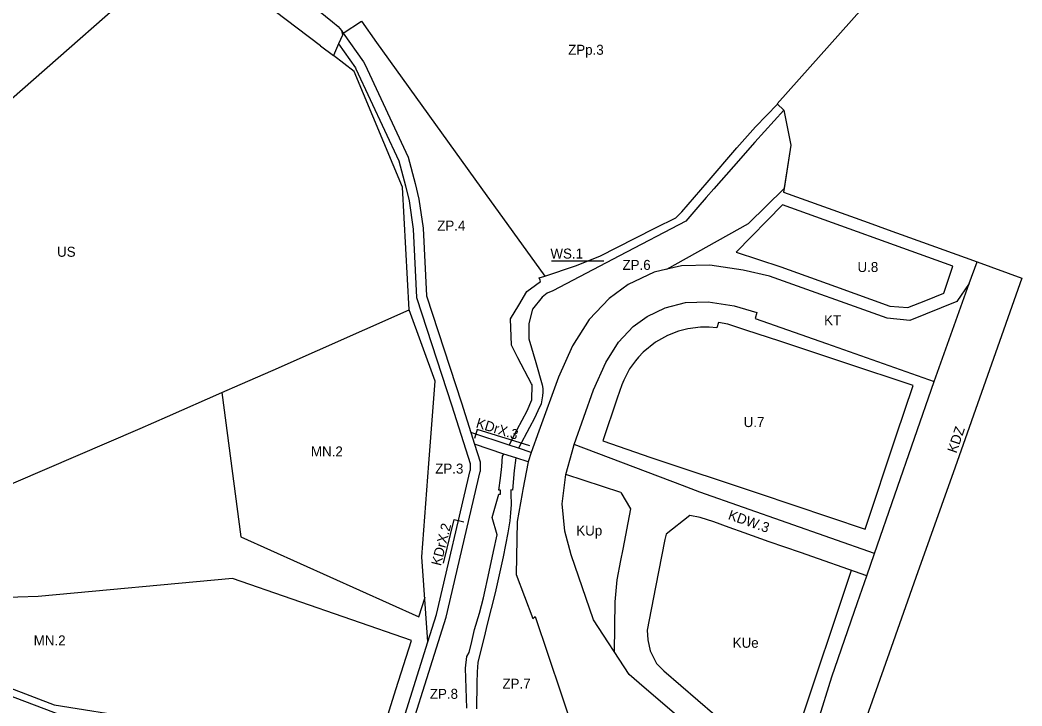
# Model space of a CAD drawing. Extents: x 7422426 to 7423369, y 5542157 to 5542988.
# Drawn here: x 7422842.1 to 7423243.7, y 5542435.8 to 5542710.7 of the extents above; entities that cross this region are included whole.
import ezdxf

# ---------------------------------------------------------------- set-up
doc = ezdxf.new("R2010")
doc.units = 0
for name, color, linetype in [('GRANICA OBSZARU OBJĘTEGO PLANEM', 7, 'Continuous'), ('LINIE ROZGRANICZAJĄCE TERENY O RÓŻNYM PRZEZNACZENIU LUB RÓŻNYCH ZASADACH ZAGOSPODAROWANIA', 7, 'Continuous'), ('NIEPRZEKRACZALNA LINIA ZABUDOWY', 7, 'Continuous'), ('OBOWIĄZUJĄCA LINIA ZABUDOWY', 7, 'Continuous'), ('OZNACZENIA TERENÓW', 7, 'Continuous')]:
    doc.layers.add(name, color=color, linetype=linetype)

msp = doc.modelspace()

# ---------------------------------------------------------------- linework, layer by layer
at = {"layer": 'GRANICA OBSZARU OBJĘTEGO PLANEM'}
for p, q in [((7423179.79, 5542715.52), (7423145.58, 5542677.06)), ((7423145.58, 5542677.06), (7423148.22, 5542674.57)), ((7423148.22, 5542674.57), (7423150.99, 5542660.52)), ((7423150.99, 5542660.52), (7423148.13, 5542641.73)), ((7423148.13, 5542641.73), (7423182.09, 5542629.5)), ((7423182.09, 5542629.5), (7423190.12, 5542626.62)), ((7423190.12, 5542626.62), (7423220.94, 5542615.53)), ((7423220.94, 5542615.53), (7423225.67, 5542613.82)), ((7423225.67, 5542613.82), (7423243.69, 5542607.21)), ((7423243.69, 5542607.21), (7423216.87, 5542531.51)), ((7423243.69, 5542607.21), (7423243.69, 5542607.21)), ((7423216.87, 5542531.51), (7423201.18, 5542487.24))]:
    msp.add_line(p, q, dxfattribs=at)
msp.add_lwpolyline([(7423201.18, 5542487.24), (7423190.43, 5542456.94), (7423177.58, 5542420.71), (7423161.25, 5542374.63), (7423114.75, 5542243.43), (7423108.16, 5542225.13)], dxfattribs=at)
at = {"layer": 'LINIE ROZGRANICZAJĄCE TERENY O RÓŻNYM PRZEZNACZENIU LUB RÓŻNYCH ZASADACH ZAGOSPODAROWANIA'}
for p, q in [((7423179.79, 5542715.52), (7423145.58, 5542677.06)), ((7422970.89, 5542706.45), (7422971.61, 5542705.43)), ((7422971.61, 5542705.43), (7422979.75, 5542693.91)), ((7422962.53, 5542700.33), (7422967.67, 5542696.44)), ((7422969.75, 5542701.14), (7422976.49, 5542691.61)), ((7422976.49, 5542691.61), (7422976.65, 5542691.2)), ((7423148.22, 5542674.57), (7423150.99, 5542660.52)), ((7423148.13, 5542641.73), (7423182.09, 5542629.5)), ((7423182.09, 5542629.5), (7423190.12, 5542626.62)), ((7423190.12, 5542626.62), (7423220.94, 5542615.53)), ((7423220.94, 5542615.53), (7423225.67, 5542613.82)), ((7423225.67, 5542613.82), (7423243.69, 5542607.21)), ((7423243.69, 5542607.21), (7423216.87, 5542531.51)), ((7423243.69, 5542607.21), (7423243.69, 5542607.21)), ((7423038.09, 5542540.32), (7423022.74, 5542545.46)), ((7423022.74, 5542545.46), (7423024.23, 5542540.7)), ((7423041.91, 5542539.06), (7423038.09, 5542540.32)), ((7423047.01, 5542537.37), (7423041.91, 5542539.06)), ((7423045.69, 5542533.59), (7423040.75, 5542535.21)), ((7423216.87, 5542531.51), (7423201.18, 5542487.24)), ((7423026.51, 5542530.19), (7423026.46, 5542529.73)), ((7423082.89, 5542521.3), (7423086.74, 5542514.76)), ((7423005.58, 5542461.55), (7423003.1, 5542495.57))]:
    msp.add_line(p, q, dxfattribs=at)
for points in [[(7422832.16, 5542800.69), (7422847.42, 5542791.25), (7422853.13, 5542787.77), (7422861.66, 5542782.48), (7422867.97, 5542778.93), (7422873.51, 5542775.58), (7422899.93, 5542760.62), (7422913.83, 5542750.93), (7422919.53, 5542746.93), (7422923.11, 5542744.51), (7422926.94, 5542741.99), (7422928.96, 5542740.48), (7422930.97, 5542738.96), (7422933.02, 5542737.32), (7422956.03, 5542718.92), (7422961.65, 5542714.49), (7422967.27, 5542710.05), (7422969.57, 5542708.13), (7422970.89, 5542706.45), (7422971.28, 5542704.67), (7422969.75, 5542701.14)], [(7422962.53, 5542700.33), (7422953.13, 5542707.49), (7422909.13, 5542740.93), (7422828.61, 5542670.37), (7422826.22, 5542668.28), (7422756.42, 5542607.12), (7422753.89, 5542609.98), (7422748.09, 5542605.15), (7422750.79, 5542602.05), (7422724.44, 5542579.24), (7422736.01, 5542566.48), (7422683.33, 5542519.83)], [(7422971.61, 5542705.43), (7422978.93, 5542710.32), (7422985.01, 5542701.76), (7423026.83, 5542643.58), (7423052.4, 5542608.01)], [(7422969.75, 5542701.14), (7422967.67, 5542696.44)], [(7422998.01, 5542594.6), (7422998.01, 5542594.6), (7422995.34, 5542643.73), (7422976.03, 5542690.08), (7422967.67, 5542696.44)], [(7422979.75, 5542693.91), (7422979.75, 5542693.91), (7422980.24, 5542692.97), (7422997.72, 5542655.71), (7423000.51, 5542645.26), (7423001.99, 5542638.96), (7423003.63, 5542627.28), (7423004.99, 5542600.19), (7423018.97, 5542557.27), (7423022.74, 5542545.46)], [(7422976.65, 5542691.2), (7422976.65, 5542691.2), (7422976.65, 5542691.2), (7422993.95, 5542654.34), (7422996.63, 5542644.28), (7422998.06, 5542638.22), (7422999.65, 5542626.9), (7423001.02, 5542599.46), (7423015.16, 5542556.04), (7423022.5, 5542533.02), (7423022.51, 5542530.18)], [(7423038.09, 5542540.32), (7423041.28, 5542546.54), (7423045.4, 5542554.05), (7423047.16, 5542558.49), (7423047.34, 5542564.51), (7423047.08, 5542564.88), (7423041.66, 5542575.32), (7423039.08, 5542580.36), (7423038.71, 5542590.94), (7423041.96, 5542596.44), (7423045.2, 5542601.93), (7423048.63, 5542604.39), (7423050.67, 5542605.86), (7423050.52, 5542606.43), (7423050.12, 5542607.35), (7423052.39, 5542608.11), (7423064.78, 5542612.26), (7423074.52, 5542616.12), (7423088.7, 5542623.35), (7423096.8, 5542627.4), (7423104.9, 5542631.45), (7423107.37, 5542633.78), (7423117.5, 5542645.54), (7423129.38, 5542659.5), (7423136.82, 5542667.91), (7423145.74, 5542676.95)], [(7423145.58, 5542677.06), (7423145.74, 5542676.95), (7423148.22, 5542674.57)], [(7423148.22, 5542674.57), (7423136.56, 5542661.7), (7423128.04, 5542652.01), (7423120.16, 5542643.05), (7423117.1, 5542639.57), (7423113.71, 5542635.72), (7423109.01, 5542630.16), (7423082.36, 5542616.2), (7423055.7, 5542602.24), (7423053.42, 5542601.26), (7423051.38, 5542599.64), (7423047.43, 5542594.82), (7423045.97, 5542589.09), (7423045.99, 5542582.97), (7423048.79, 5542573.48), (7423051.36, 5542564.56), (7423051.68, 5542563.06), (7423051.61, 5542561.56), (7423051.53, 5542560.06), (7423050.95, 5542556.92), (7423049.68, 5542554.03), (7423048.3, 5542551.13), (7423046.32, 5542547.39), (7423041.91, 5542539.06)], [(7423150.99, 5542660.52), (7423148.35, 5542643.16), (7423148.13, 5542641.73)], [(7423101.4, 5542610.83), (7423134.13, 5542629.16), (7423148.35, 5542643.16), (7423148.35, 5542643.16)], [(7423222.54, 5542605.06), (7423217.55, 5542597.91), (7423198.7, 5542590.35), (7423189.68, 5542591.17), (7423142.47, 5542608.06), (7423131.96, 5542610.5), (7423118.54, 5542612.52), (7423107.25, 5542612.24), (7423101.4, 5542610.83)], [(7423184.59, 5542496.92), (7423192.73, 5542520.4), (7423208.56, 5542565.83), (7423222.54, 5542605.06), (7423225.67, 5542613.82)], [(7423101.4, 5542610.83), (7423096.31, 5542609.61), (7423085.86, 5542604.77), (7423078.16, 5542599.08), (7423070.26, 5542590.69), (7423063.59, 5542580.2), (7423057.85, 5542567.59), (7423050.03, 5542545.98), (7423047.01, 5542537.37), (7423045.69, 5542533.59), (7423043.68, 5542522.52)], [(7423144.59, 5542398.03), (7423130.24, 5542410.43), (7423121.3, 5542418.45), (7423104.3, 5542432.93), (7423092.28, 5542443.17), (7423086.26, 5542448.39), (7423071.89, 5542470.3), (7423063.04, 5542496.35), (7423060.47, 5542505.88), (7423059.44, 5542516.76), (7423060.83, 5542528.59), (7423063.4, 5542537.59), (7423064.24, 5542540.58), (7423071.96, 5542562.51), (7423076.84, 5542573.46), (7423081.97, 5542581.66), (7423087.85, 5542587.89), (7423093.39, 5542591.88), (7423100.66, 5542595.42), (7423108.86, 5542597.47), (7423117.92, 5542597.74), (7423128.28, 5542596.1), (7423137.46, 5542593.45)], [(7422901.23, 5542551.84), (7422923.01, 5542561.41), (7422930.3, 5542564.67), (7422943.58, 5542570.44), (7422998.01, 5542594.6)], [(7423003.1, 5542495.57), (7423005.96, 5542532.98), (7423008.48, 5542565.97), (7422998.01, 5542594.6)], [(7423137.46, 5542593.45), (7423136.73, 5542591.11), (7423165.33, 5542581.05), (7423208.56, 5542565.83)], [(7422827.06, 5542519.82), (7422890.28, 5542547.05), (7422901.23, 5542551.84), (7422901.23, 5542551.84)], [(7423024.23, 5542540.7), (7423026.5, 5542533.65), (7423026.51, 5542530.19)], [(7423040.75, 5542535.21), (7423036.03, 5542536.78), (7423024.23, 5542540.7)], [(7423184.59, 5542496.92), (7423114.54, 5542521.49), (7423107.6, 5542524.13), (7423064.24, 5542540.58)], [(7423021.21, 5542434.85), (7423020.6, 5542450.91), (7423021.19, 5542455.68), (7423022.04, 5542457.19), (7423023.19, 5542461.57), (7423024.28, 5542466.42), (7423026.26, 5542473), (7423027.88, 5542479.15), (7423030.11, 5542489.49), (7423031.88, 5542497.7), (7423033.29, 5542504.33), (7423031.37, 5542511.28), (7423034, 5542520.7), (7423034.67, 5542520.74), (7423034.65, 5542522.24), (7423034.04, 5542522.22), (7423034.6, 5542527.03), (7423035.16, 5542531.83), (7423035.45, 5542535.98), (7423036.04, 5542536.78)], [(7423040.75, 5542535.21), (7423040.14, 5542530.19), (7423039.41, 5542522.35), (7423038.84, 5542522.37), (7423038.86, 5542520.87), (7423038.93, 5542516.55), (7423038.67, 5542513.24), (7423038.42, 5542509.95), (7423037.66, 5542505.15), (7423036.69, 5542500.38), (7423035.71, 5542495.61), (7423034.6, 5542490.7), (7423032.51, 5542481.18), (7423030.94, 5542474.87), (7423029.37, 5542468.55), (7423028.5, 5542465.05), (7423027.8, 5542462.27), (7423026.54, 5542457.11), (7423025.58, 5542453.16), (7423025.25, 5542449.42), (7423025.19, 5542444.95), (7423025.04, 5542434.67)], [(7422988.43, 5542394), (7422991.92, 5542404.83), (7423012.86, 5542471.45), (7423026.46, 5542529.73)], [(7423005.58, 5542461.55), (7423009, 5542472.51), (7423022.51, 5542530.18)], [(7423082.89, 5542521.3), (7423060.83, 5542528.59)], [(7423043.39, 5542521.01), (7423041.35, 5542509.72), (7423040.98, 5542488.52), (7423047.58, 5542470.88)], [(7423043.68, 5542522.52), (7423043.39, 5542521.01)], [(7423086.74, 5542514.76), (7423083.66, 5542498.58), (7423082.81, 5542494.09), (7423081.32, 5542486.29), (7423080.48, 5542477.47), (7423080.26, 5542457.53)], [(7423110.52, 5542512.17), (7423101.05, 5542504.62), (7423100.57, 5542502.53), (7423096.85, 5542483.36), (7423093.52, 5542466.18), (7423093.68, 5542462.25), (7423094.64, 5542457.86), (7423097.2, 5542452.8), (7423100.2, 5542449.94), (7423134.17, 5542420.54), (7423143.55, 5542414.35), (7423147.72, 5542413.7), (7423151.91, 5542416.05)], [(7423181.49, 5542487.98), (7423154.9, 5542497.25), (7423142.34, 5542501.64), (7423132.32, 5542505.24), (7423126.38, 5542507.36), (7423120.12, 5542509.58), (7423114.76, 5542511.29), (7423110.52, 5542512.17)], [(7423181.5, 5542488), (7423184.59, 5542496.92)], [(7423138.42, 5542348.62), (7423138.42, 5542348.62), (7423150.26, 5542380.3), (7423150.23, 5542387.98), (7423144.59, 5542398.03), (7423139.98, 5542402), (7423147.72, 5542413.7), (7423154.32, 5542417.39), (7423157.8, 5542419.8), (7423159.27, 5542421.67), (7423161.94, 5542429.82), (7423167.46, 5542447.53), (7423177.78, 5542477.28), (7423181.5, 5542488)], [(7423201.18, 5542487.24), (7423190.43, 5542456.94), (7423177.58, 5542420.71), (7423161.25, 5542374.63), (7423114.75, 5542243.43), (7423108.16, 5542225.13)], [(7423047.58, 5542470.88), (7423048.58, 5542471.61), (7423064.13, 5542425.21), (7423063.72, 5542424.34)], [(7422859.52, 5542431.68), (7422819.5, 5542446.77), (7422735.96, 5542460.38)], [(7422985.19, 5542396.96), (7422988.11, 5542406.04), (7423005.58, 5542461.55)]]:
    msp.add_lwpolyline(points, dxfattribs=at)
at = {"layer": 'NIEPRZEKRACZALNA LINIA ZABUDOWY'}
for p, q in [((7423122.06, 5542589.44), (7423121.35, 5542587.33)), ((7422930.63, 5542503.54), (7423001.93, 5542471.52)), ((7423150.22, 5542414.99), (7423175.3, 5542490.18)), ((7422849.38, 5542479.64), (7422751.17, 5542476.22))]:
    msp.add_line(p, q, dxfattribs=at)
for points in [[(7423147.76, 5542636.61), (7423129.07, 5542617.68), (7423147.04, 5542611.74)], [(7423215.97, 5542612), (7423215.97, 5542612), (7423147.76, 5542636.61)], [(7423147.04, 5542611.74), (7423147.04, 5542611.74), (7423168.9, 5542603.91), (7423190.77, 5542596.09), (7423197.95, 5542595.44), (7423205.17, 5542598.33), (7423212.38, 5542601.22)], [(7423200.03, 5542564.24), (7423172.69, 5542573.37), (7423146.7, 5542582.03), (7423133.07, 5542586.38), (7423125.74, 5542588.76), (7423122.06, 5542589.44)], [(7423121.35, 5542587.33), (7423121.35, 5542587.33), (7423118.34, 5542587.59), (7423114.78, 5542587.57), (7423109.79, 5542586.94), (7423106.04, 5542585.97), (7423101.64, 5542584.26), (7423096.85, 5542581.58), (7423091.83, 5542577.61), (7423090.03, 5542575.61), (7423088.72, 5542574.14), (7423086.38, 5542570.87), (7423084.1, 5542566.38), (7423083.26, 5542564.51), (7423081.41, 5542559.1), (7423075.7, 5542542.05)], [(7422923.01, 5542561.41), (7422930.63, 5542503.54)], [(7423075.7, 5542542.05), (7423094.98, 5542535.39), (7423137.9, 5542521.04), (7423180.82, 5542506.7)], [(7422998.99, 5542462.03), (7422927.25, 5542486.87), (7422849.38, 5542479.64)], [(7423001.93, 5542471.52), (7423004.41, 5542479.42)], [(7422726.51, 5542465.58), (7422731.44, 5542464.31), (7422736.44, 5542463.34), (7422778.36, 5542456.51), (7422820.28, 5542449.69), (7422838.01, 5542443), (7422855.74, 5542436.31), (7422889.3, 5542430.97), (7422900.75, 5542429.04), (7422932.04, 5542423.65), (7422963.33, 5542418.26), (7422980.98, 5542405.05)], [(7422980.98, 5542405.05), (7422982.5, 5542409.77), (7422992.74, 5542442.33), (7422998.99, 5542462.03)]]:
    msp.add_lwpolyline(points, dxfattribs=at)
at = {"layer": 'OBOWIĄZUJĄCA LINIA ZABUDOWY'}
msp.add_line((7423212.38, 5542601.22), (7423215.97, 5542612), dxfattribs=at)
msp.add_lwpolyline([(7423180.82, 5542506.7), (7423193.3, 5542544.07), (7423200.03, 5542564.24)], dxfattribs=at)
at = {"layer": 'OZNACZENIA TERENÓW'}
msp.add_line((7423055.09, 5542614.22), (7423076.05, 5542614.22), dxfattribs=at)
for points in [[(7423046.39, 5542539.99), (7423025.34, 5542546.58), (7423024.23, 5542543.03)], [(7423011.76, 5542493), (7423016.1, 5542510.54), (7423020.01, 5542509.58)]]:
    msp.add_lwpolyline(points, dxfattribs=at)

# ---------------------------------------------------------------- texts
for s, p in [('ZPp.3', (7423061.77, 5542696.79)), ('ZP.4', (7423009.3, 5542626.31)), ('US', (7422856.92, 5542615.82)), ('WS.1', (7423054.68, 5542615.11)), ('ZP.6', (7423083.56, 5542610.57)), ('U.8', (7423177.77, 5542609.72)), ('KT', (7423164.38, 5542588.38)), ('U.7', (7423132.14, 5542547.58)), ('MN.2', (7422958.68, 5542535.79)), ('ZP.3', (7423008.5, 5542528.93)), ('KUp', (7423065.03, 5542504.11)), ('MN.2', (7422847.56, 5542460.07)), ('KUe', (7423127.74, 5542459.12)), ('ZP.7', (7423035.44, 5542442.72)), ('ZP.8', (7423006.34, 5542438.66))]:
    msp.add_text(s, height=4, dxfattribs=at).set_placement(p)
for s, rotation, p in [('KDrX.3', 342.8106, (7423024.56, 5542547.54)), ('KDZ', 71.1624, (7423217.43, 5542536.83)), ('KDW.3', 340.6703, (7423125.61, 5542510.75)), ('KDrX.2', 75.7981, (7423010.73, 5542491.72))]:
    msp.add_text(s, height=4, rotation=rotation, dxfattribs=at).set_placement(p)

doc.saveas('drawing.dxf')
